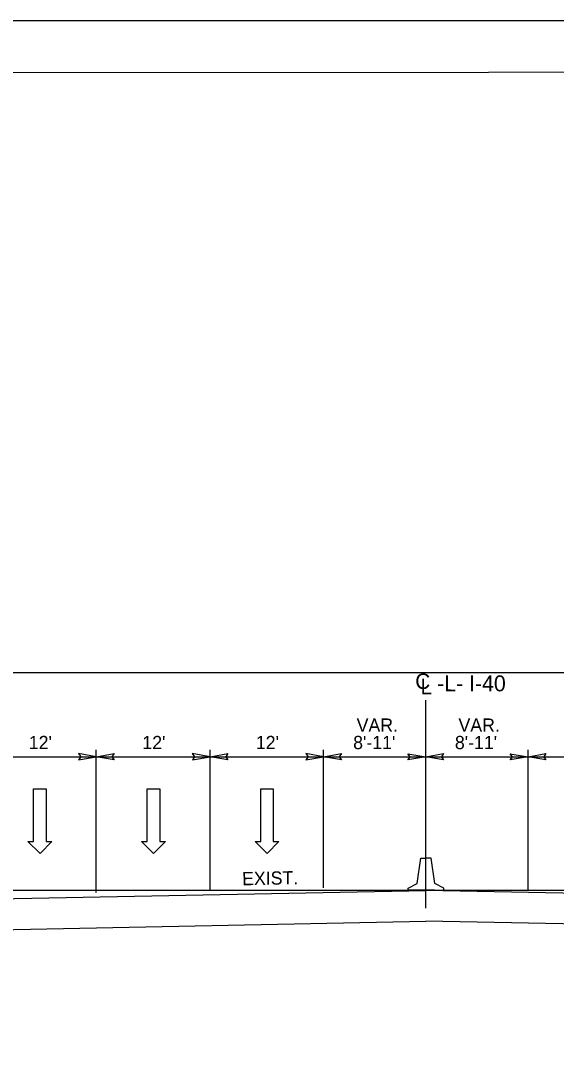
# Model space of a CAD drawing. Extents: x 1727387 to 1728895, y 539219 to 540208.
# Drawn here: x 1727520.2 to 1727576.9, y 539479.4 to 539589 of the extents above; entities that cross this region are included whole.
import ezdxf

# ---------------------------------------------------------------- set-up
doc = ezdxf.new("R2010")
doc.units = 0
for name, color, linetype in [('Default', 7, 'Continuous'), ('Overhead Sheet Border', 7, 'Continuous'), ('Sheet Plot Border Outside CELL', 7, 'Continuous'), ('Typical Pavement Slope CELL', 7, 'Continuous'), ('Typical Pavement Slope Information CELL', 7, 'Continuous'), ('Typical Text Centerline CELL', 7, 'Continuous')]:
    doc.layers.add(name, color=color, linetype=linetype)

msp = doc.modelspace()

# ---------------------------------------------------------------- linework, layer by layer
at = {"layer": 'Default'}
for p, q in [((1727481.19, 539520.12), (1727608.75, 539520.12)), ((1727528.24, 539496.87), (1727528.24, 539511.95)), ((1727540.27, 539497.11), (1727540.27, 539511.95)), ((1727552.28, 539497.35), (1727552.28, 539511.95)), ((1727573.9, 539497.16), (1727573.9, 539511.95)), ((1727516.25, 539511.21), (1727528.26, 539511.21)), ((1727528.26, 539511.21), (1727540.27, 539511.21)), ((1727540.27, 539511.21), (1727552.28, 539511.21)), ((1727552.28, 539511.21), (1727563.08, 539511.21)), ((1727563.08, 539511.21), (1727573.92, 539511.21)), ((1727573.92, 539511.21), (1727585.93, 539511.21)), ((1727521.61, 539502.23), (1727521.61, 539507.83)), ((1727521.61, 539507.83), (1727522.93, 539507.83)), ((1727522.93, 539507.83), (1727522.93, 539502.23)), ((1727533.62, 539502.23), (1727533.62, 539507.83)), ((1727533.62, 539507.83), (1727534.94, 539507.83)), ((1727534.94, 539507.83), (1727534.94, 539502.23)), ((1727545.63, 539502.23), (1727545.63, 539507.83)), ((1727545.63, 539507.83), (1727546.95, 539507.83)), ((1727546.95, 539507.83), (1727546.95, 539502.23)), ((1727522.29, 539500.97), (1727521.01, 539502.23)), ((1727521.01, 539502.23), (1727521.61, 539502.23)), ((1727523.53, 539502.23), (1727522.29, 539500.97)), ((1727522.93, 539502.23), (1727523.53, 539502.23)), ((1727534.3, 539500.97), (1727533.02, 539502.23)), ((1727533.02, 539502.23), (1727533.62, 539502.23)), ((1727535.54, 539502.23), (1727534.3, 539500.97)), ((1727534.94, 539502.23), (1727535.54, 539502.23)), ((1727546.31, 539500.97), (1727545.03, 539502.23)), ((1727545.03, 539502.23), (1727545.63, 539502.23)), ((1727547.55, 539502.23), (1727546.31, 539500.97)), ((1727546.95, 539502.23), (1727547.55, 539502.23)), ((1727653.65, 539497.08), (1727481.19, 539497.08))]:
    msp.add_line(p, q, dxfattribs=at)
for points in [[(1727526.37, 539510.89), (1727528.24, 539511.21), (1727526.36, 539511.54), (1727526.6, 539511.21)], [(1727530.12, 539510.89), (1727528.24, 539511.21), (1727530.13, 539511.54), (1727529.89, 539511.21)], [(1727538.4, 539510.89), (1727540.27, 539511.21), (1727538.39, 539511.54), (1727538.63, 539511.21)], [(1727542.15, 539510.89), (1727540.27, 539511.21), (1727542.16, 539511.54), (1727541.92, 539511.21)], [(1727550.41, 539510.89), (1727552.28, 539511.21), (1727550.39, 539511.54), (1727550.63, 539511.21)], [(1727554.16, 539510.89), (1727552.28, 539511.21), (1727554.17, 539511.54), (1727553.93, 539511.21)], [(1727561.2, 539511.53), (1727563.08, 539511.21), (1727561.19, 539510.88), (1727561.43, 539511.21)], [(1727564.96, 539510.89), (1727563.08, 539511.21), (1727564.97, 539511.54), (1727564.73, 539511.21)], [(1727572.02, 539511.53), (1727573.9, 539511.21), (1727572.01, 539510.88), (1727572.25, 539511.21)], [(1727575.77, 539510.89), (1727573.9, 539511.21), (1727575.79, 539511.54), (1727575.55, 539511.21)]]:
    msp.add_lwpolyline(points, close=True, dxfattribs=at)
at = {"layer": 'Overhead Sheet Border'}
msp.add_lwpolyline([(1727719.57, 539583.63), (1727419.83, 539583.47), (1727419.94, 539373.65), (1727719.68, 539373.81)], close=True, dxfattribs=at)
at = {"layer": 'Sheet Plot Border Outside CELL'}
msp.add_lwpolyline([(1727723.82, 539589.02), (1727387.25, 539589.02), (1727387.25, 539369.85), (1727723.82, 539369.85)], close=True, dxfattribs=at)
at = {"layer": 'Typical Pavement Slope CELL'}
for p, q in [((1727562.16, 539497.8), (1727562.56, 539500.5)), ((1727562.56, 539500.5), (1727563.1, 539500.5)), ((1727563.64, 539500.5), (1727563.1, 539500.5)), ((1727564.04, 539497.8), (1727563.64, 539500.5)), ((1727516.23, 539496.14), (1727563.08, 539497.08)), ((1727609.93, 539496.14), (1727563.08, 539497.08)), ((1727516.23, 539492.89), (1727563.08, 539493.83)), ((1727597.27, 539493.14), (1727563.08, 539493.83))]:
    msp.add_line(p, q, dxfattribs=at)
for points in [[(1727564.01, 539497.09), (1727561.22, 539497.09), (1727561.22, 539497.31), (1727562.16, 539497.8)], [(1727562.19, 539497.09), (1727564.98, 539497.09), (1727564.98, 539497.31), (1727564.04, 539497.8)]]:
    msp.add_lwpolyline(points, dxfattribs=at)
at = {"layer": 'Typical Text Centerline CELL'}
msp.add_line((1727563.08, 539495.19), (1727563.08, 539517.2), dxfattribs=at)

# ---------------------------------------------------------------- texts
at = {"layer": 'Typical Pavement Slope Information CELL'}
for s, p in [('VAR.', (1727555.77, 539513.85)), ('VAR.', (1727566.54, 539513.85)), ("12'", (1727521.1, 539512.01)), ("12'", (1727533.11, 539512.01)), ("12'", (1727545.11, 539512.01)), ("8'-11'", (1727555.4, 539512.01)), ("8'-11'", (1727566.16, 539512.01))]:
    msp.add_text(s, height=1.401, dxfattribs=at).set_placement(p)
msp.add_text('EXIST.', height=1.401, rotation=1.1457, dxfattribs=at).set_placement((1727543.67, 539497.61))
at = {"layer": 'Typical Text Centerline CELL'}
for s, height, rotation, p in [('C', 1.64, 0.0443, (1727561.97, 539518.37)), ('L', 1.64, 359.9912, (1727562.52, 539517.81)), ('-L- I-40', 1.684, 359.9417, (1727564.28, 539518.13))]:
    msp.add_text(s, height=height, rotation=rotation, dxfattribs=at).set_placement(p)

doc.saveas('drawing.dxf')
